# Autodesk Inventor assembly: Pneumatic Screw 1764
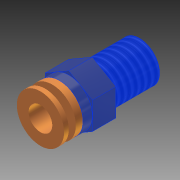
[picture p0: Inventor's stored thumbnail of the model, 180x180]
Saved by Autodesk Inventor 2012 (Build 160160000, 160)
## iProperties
Created: 2010-02
Part Number: Pneumatic Screw 1764
Document SubType Name: Assembly
Designer: clee1
Author: clee1
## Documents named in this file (3)
- R:\CAD Archives\Pneumatics_1764\Accumulator_1764\Pneumatic_Screw_1764\Pneumatic_Screw_1764.iam
- R:\CAD Archives\Pneumatics_1764\Accumulator_1764\Pneumatic_Screw_1764\Pneumatic_Screw_Part_1_1764.ipt
- R:\CAD Archives\Pneumatics_1764\Accumulator_1764\Pneumatic_Screw_1764\Pneumatic_Screw_Part_2_1764.ipt
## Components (2 placed, 2 different names)
1. Pneumatic_Screw_Part_1_1764:1 — Insert:1
2. Pneumatic_Screw_Part_2_1764:1 — Insert:1
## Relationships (1: Insert 1)
- Insert:1: Pneumatic_Screw_Part_1_1764:1 ↔ Pneumatic_Screw_Part_2_1764:1
